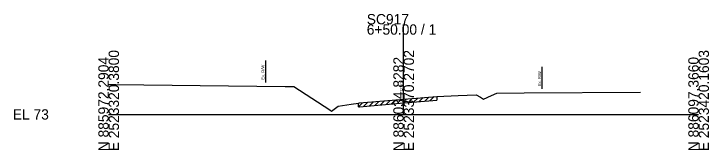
# Model space of a CAD drawing. Extents: x -26 to 218, y -10 to 12021.
# Drawn here: x -25.7 to 162.8, y 6490.3 to 6527.3 of the extents above; entities that cross this region are included whole.
import ezdxf

# ---------------------------------------------------------------- set-up
doc = ezdxf.new("R2010")
doc.units = 0
for name, color, linetype in [('RD_GPK_XS_Cell', 7, 'Continuous'), ('RD_XS_ExGround', 7, 'Continuous'), ('RD_XS_ExPaveRet', 7, 'Continuous'), ('RD_XS_ExRW', 7, 'Continuous'), ('RD_XS_TX_Elev_EX', 7, 'Continuous')]:
    doc.layers.add(name, color=color, linetype=linetype)

msp = doc.modelspace()

# ---------------------------------------------------------------- linework, layer by layer
at = {"layer": 'RD_GPK_XS_Cell'}
for p, q in [((80, 6500), (80, 6524.45)), ((0, 6500), (80, 6500)), ((80, 6500), (160, 6500))]:
    msp.add_line(p, q, dxfattribs=at)
at = {"layer": 'RD_XS_ExGround'}
for p, q in [((0, 6508.15), (1.91, 6508.12)), ((1.91, 6508.12), (24.86, 6507.88)), ((24.86, 6507.88), (47.89, 6507.58)), ((47.89, 6507.58), (50.24, 6507.55)), ((50.24, 6507.55), (59.95, 6501.21)), ((80, 6504.12), (83.48, 6504.42)), ((83.48, 6504.42), (89.03, 6504.9)), ((89.03, 6504.9), (94.8, 6505.16)), ((94.8, 6505.16), (99.68, 6505.35)), ((99.68, 6505.35), (100.81, 6504.67)), ((100.81, 6504.67), (101.63, 6504.15)), ((101.63, 6504.15), (103.82, 6505.15)), ((103.82, 6505.15), (105.32, 6505.77)), ((105.32, 6505.77), (112.67, 6505.87)), ((112.67, 6505.87), (144.25, 6506.05)), ((62.26, 6502.27), (65.8, 6502.79)), ((65.8, 6502.79), (67.72, 6503.07)), ((67.72, 6503.07), (68.04, 6503.1)), ((68.04, 6503.1), (79.02, 6504.03)), ((79.02, 6504.03), (80, 6504.12)), ((59.95, 6501.21), (60.41, 6500.91)), ((60.41, 6500.91), (62.26, 6502.27))]:
    msp.add_line(p, q, dxfattribs=at)
at = {"layer": 'RD_XS_ExPaveRet'}
for p, q in [((82.72, 6503.36), (83.81, 6504.45)), ((84.22, 6503.49), (85.31, 6504.58)), ((85.72, 6503.62), (86.81, 6504.71)), ((87.22, 6503.75), (88.31, 6504.84)), ((89.03, 6504.9), (89.03, 6503.9)), ((67.72, 6502.07), (68.81, 6503.16)), ((67.72, 6502.07), (67.72, 6503.07)), ((68.04, 6502.1), (79.02, 6503.03)), ((69.22, 6502.2), (70.31, 6503.29)), ((70.72, 6502.32), (71.81, 6503.42)), ((72.22, 6502.45), (73.31, 6503.55)), ((73.72, 6502.58), (74.81, 6503.67)), ((75.22, 6502.71), (76.31, 6503.8)), ((76.72, 6502.84), (77.81, 6503.93)), ((78.22, 6502.97), (79.31, 6504.06)), ((79.02, 6503.03), (80, 6503.12)), ((79.72, 6503.09), (80.81, 6504.19)), ((80, 6503.12), (83.48, 6503.42)), ((81.22, 6503.23), (82.31, 6504.32)), ((83.48, 6503.42), (89.03, 6503.9)), ((67.72, 6502.07), (68.04, 6502.1))]:
    msp.add_line(p, q, dxfattribs=at)
at = {"layer": 'RD_XS_ExRW'}
for p, q in [((42.5, 6514.65), (42.5, 6508.65)), ((117.5, 6512.9), (117.5, 6506.9))]:
    msp.add_line(p, q, dxfattribs=at)

# ---------------------------------------------------------------- texts
at = {"layer": 'RD_GPK_XS_Cell'}
for s, p in [('SC917', (70, 6524.45)), ('6+50.00 / 1', (70, 6521.65)), ('EL 73', (-26, 6498.6))]:
    msp.add_text(s, height=2.8, dxfattribs=at).set_placement(p)
for s, p in [('E 2523320.3800', (2.8, 6490)), ('E 2523370.2702', (82.8, 6490)), ('E 2523420.1603', (162.8, 6490)), ('N 885972.2904', (0, 6490)), ('N 886034.8282', (80, 6490)), ('N 886097.3660', (160, 6490))]:
    msp.add_text(s, height=2.8, rotation=90, dxfattribs=at).set_placement(p)
at = {"layer": 'RD_XS_ExRW'}
for p in [(42.25, 6509.44), (117.25, 6507.68)]:
    msp.add_text('Ex. R/W ', height=0.8, rotation=90, dxfattribs=at).set_placement(p)
at = {"layer": 'RD_XS_TX_Elev_EX'}
msp.add_text('77.12', height=0.8, rotation=90, dxfattribs=at).set_placement((79.9, 6506.12))

doc.saveas('drawing.dxf')
